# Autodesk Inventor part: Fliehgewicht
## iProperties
Shininess: 20.0
Angle Display Precision: 2
Document Length Units: 11269
Document Angle Units: 11279
Document Time Units: 11290
Document Mass Units: 11283
Document Length Units Precision: 3
Document Angle Units Precision: 2
Created: 2003-02
Part Number: Fliehgewicht
Material: S275JR
Document SubType Name: Modellieren
Designer: Administrator
Density: 0.0
Volumn: 0.0
Area: 0.0
PropertySet Name: Model Information
Control State: 0
Master: False
Checked Out: False
Author: Administrator
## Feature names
1. Grundkörper [Extrusion]
2. Bohrung Kerbstift [Hole]
3. Bohrung  Zugfeder [Hole]
4. Bohrung Zylinderstift [Hole]
5. Fase1 [Chamfer]
